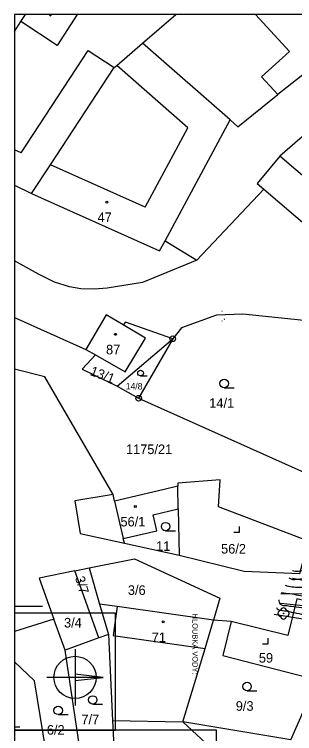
# Model space of a CAD drawing. Extents: x -564091 to -563943, y -1163604 to -1163394.
# Drawn here: x -564091.1 to -564041.3, y -1163521.5 to -1163393.9 of the extents above; entities that cross this region are included whole.
import ezdxf

# ---------------------------------------------------------------- set-up
doc = ezdxf.new("R2010")
doc.units = 0
for name, color, linetype in [('_rám PRU1 a PRI1', 7, 'Continuous'), ('Hranice parcel', 7, 'Continuous'), ('Parcelní čísla', 7, 'Continuous'), ('Vnitřní kresba', 7, 'Continuous'), ('Vrstva 14', 7, 'Continuous'), ('Vrstva 22', 7, 'Continuous'), ('Vrstva 24', 7, 'Continuous'), ('Vrstva 26', 7, 'Continuous'), ('Značky bodu BP', 7, 'Continuous'), ('Značky budov', 7, 'Continuous'), ('Značky kultur', 7, 'Continuous')]:
    doc.layers.add(name, color=color, linetype=linetype)

msp = doc.modelspace()

# ---------------------------------------------------------------- linework, layer by layer
for p, q in [((-564054.1945627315, -1163446.636668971), (-564054.2954721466, -1163446.641197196)), ((-564054.1918225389, -1163448.3497116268), (-564054.2927319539, -1163448.3542398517)), ((-564053.7909211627, -1163448.0049589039), (-564053.8918305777, -1163448.0094871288))]:
    msp.add_line(p, q)
at = {"layer": '_rám PRU1 a PRI1'}
for p, q in [((-564091.1178187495, -1163393.9081689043), (-564091.1178187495, -1163603.908169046)), ((-563942.617818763, -1163393.9081689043), (-564091.1178187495, -1163393.9081689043)), ((-564091.1178187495, -1163498.9081689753), (-564086.1178187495, -1163498.9081689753)), ((-564073.1724956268, -1163500.11602324), (-564091.1178187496, -1163500.1077130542)), ((-564091.1178187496, -1163500.1077130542), (-564091.1178187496, -1163520.8811005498)), ((-564073.1724956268, -1163520.8811005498), (-564073.1724956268, -1163500.11602324)), ((-564080.3449498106, -1163506.5280350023), (-564080.3449498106, -1163516.5280350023)), ((-564075.3449498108, -1163511.5280350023), (-564080.3449498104, -1163510.9530350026)), ((-564075.3449498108, -1163511.5280350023), (-564085.3449498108, -1163511.5280350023)), ((-564055.2271725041, -1163520.8811005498), (-564091.1178187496, -1163520.8811005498)), ((-564091.1178187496, -1163520.8811005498), (-564091.1178187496, -1163603.908169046)), ((-564091.1178187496, -1163520.8811005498), (-564073.1724956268, -1163520.8811005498)), ((-564055.2271725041, -1163603.908169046), (-564055.2271725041, -1163520.8811005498))]:
    msp.add_line(p, q, dxfattribs=at)
msp.add_lwpolyline([(-564075.3449498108, -1163511.5280350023), (-564080.3449498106, -1163511.5280350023), (-564080.3449498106, -1163512.1030350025)], close=True, dxfattribs=at)
msp.add_circle((-564080.3449498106, -1163511.5280350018), 3.750000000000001, dxfattribs=at)
at = {"layer": 'Hranice parcel'}
for p, q in [((-564091.1178187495, -1163424.1901119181), (-564088.0600000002, -1163425.6700000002)), ((-564058.7000000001, -1163437.5200000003), (-564046.8300000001, -1163424.9100000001)), ((-564046.8300000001, -1163424.9100000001), (-564025.3400000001, -1163443.25)), ((-564064.31, -1163434.0900000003), (-564058.7000000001, -1163437.5200000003)), ((-564058.7000000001, -1163437.5200000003), (-564068.36, -1163441.46)), ((-564074.8, -1163447.22), (-564078.4, -1163453.3300000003)), ((-564071.8, -1163448.98), (-564074.8, -1163447.22)), ((-564067.8200000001, -1163451.3300000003), (-564071.8, -1163448.98)), ((-564071.4200000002, -1163457.34), (-564067.8200000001, -1163451.3300000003)), ((-564072.88, -1163459.86), (-564063.0000000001, -1163451.45)), ((-564063.0000000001, -1163451.45), (-564069.05, -1163462)), ((-564078.4, -1163453.3300000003), (-564076.72, -1163454.3200000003)), ((-564076.72, -1163454.3200000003), (-564071.4200000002, -1163457.34)), ((-564072.88, -1163459.86), (-564069.05, -1163462)), ((-564069.05, -1163462), (-564039.04, -1163475.4300000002)), ((-564062.0000000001, -1163481.6300000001), (-564062.0700000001, -1163477.6300000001)), ((-564062.0000000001, -1163481.6300000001), (-564061.85, -1163489.8700000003)), ((-564071.5700000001, -1163487.74), (-564061.85, -1163489.8700000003)), ((-564080.36, -1163492.6300000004), (-564077.8600000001, -1163492.12)), ((-564077.8600000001, -1163492.12), (-564075.98, -1163498.54)), ((-564076.1, -1163504.52), (-564080.36, -1163492.6300000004)), ((-564075.98, -1163498.54), (-564074.41, -1163503.9000000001)), ((-564084.1, -1163501.1700000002), (-564091.1178187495, -1163503.3904184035)), ((-564082.12, -1163506.7), (-564084.1, -1163501.1700000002)), ((-564052.5900000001, -1163501.62), (-564055.7800000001, -1163501.3900000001)), ((-564076.1, -1163504.52), (-564082.12, -1163506.7)), ((-564074.41, -1163503.9000000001), (-564076.1, -1163504.52)), ((-564074.41, -1163503.9000000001), (-564073.7100000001, -1163519.1600000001)), ((-564078.72, -1163529.1500000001), (-564082.12, -1163506.7)), ((-564042.03, -1163522.61), (-564037.3400000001, -1163511.95)), ((-564073.7100000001, -1163519.1600000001), (-564061.18, -1163519.3900000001)), ((-564042.03, -1163522.61), (-564061.18, -1163519.3900000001))]:
    msp.add_line(p, q, dxfattribs=at)
for points in [[(-564091.1178187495, -1163396.9348794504), (-564089.99, -1163395.2), (-564089.1477261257, -1163393.9081689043)], [(-564088.0600000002, -1163425.6700000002), (-564084.72, -1163420.59), (-564073.39, -1163403.36), (-564072.9400000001, -1163402.97), (-564068.35, -1163399.01), (-564062.4303181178, -1163393.9081689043)], [(-564044.3500000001, -1163408.1300000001), (-564047.22, -1163404.99), (-564042.28, -1163400.47), (-564048.2735600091, -1163393.9081689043)], [(-564016.0603817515, -1163393.9081689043), (-564018.3400000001, -1163396.8800000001), (-564043.9700000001, -1163419.09), (-564048.02, -1163423.8900000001), (-564046.8300000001, -1163424.9100000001)], [(-564023.206475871, -1163393.9081689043), (-564033.27, -1163399.45), (-564044.3500000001, -1163408.1300000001)], [(-564064.31, -1163434.0900000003), (-564052.8, -1163412.6400000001), (-564051.4500000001, -1163413.83), (-564044.3500000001, -1163408.1300000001)], [(-564088.0600000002, -1163425.6700000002), (-564065.3300000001, -1163435.84), (-564064.31, -1163434.0900000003)], [(-564068.36, -1163441.46), (-564074.6300000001, -1163442.46), (-564076.93, -1163442.6700000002), (-564079.29, -1163442.57), (-564081.35, -1163442.23), (-564084.01, -1163441.4000000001), (-564086.8400000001, -1163439.97), (-564091.1178187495, -1163437.610531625)], [(-564030.62, -1163449.1700000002), (-564050.55, -1163447.07), (-564055.2000000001, -1163447.28), (-564061.43, -1163449.5000000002), (-564063.0000000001, -1163451.45)], [(-564091.1178187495, -1163447.6580384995), (-564078.4, -1163453.3300000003)], [(-564063.0000000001, -1163451.45), (-564071.36, -1163448.5), (-564071.8, -1163448.98)], [(-564076.72, -1163454.3200000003), (-564079.0700000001, -1163456.87), (-564072.88, -1163459.86)], [(-564073.5900000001, -1163479.1), (-564085.6900000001, -1163458.23), (-564091.1178187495, -1163456.8425682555)], [(-564038.9, -1163487.37), (-564054.87, -1163481.26), (-564054.55, -1163476.46), (-564062.0800000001, -1163477.1), (-564062.0700000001, -1163477.6300000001)], [(-564062.0700000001, -1163477.6300000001), (-564064.51, -1163478.1700000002), (-564073.3200000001, -1163480.27), (-564073.5900000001, -1163479.1)], [(-564073.5900000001, -1163479.1), (-564080.4, -1163480.2), (-564079.43, -1163486.0000000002), (-564071.5700000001, -1163487.74)], [(-564071.5700000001, -1163487.74), (-564071.77, -1163486.8900000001), (-564065.8300000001, -1163485.5), (-564066.49, -1163482.6800000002), (-564062.0000000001, -1163481.6300000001)], [(-564061.85, -1163489.8700000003), (-564050.3300000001, -1163492.71), (-564040.4, -1163493.1), (-564038.9, -1163487.37)], [(-564077.8600000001, -1163492.12), (-564069.8100000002, -1163490.48), (-564054.63, -1163497.4700000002), (-564055.7800000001, -1163501.3900000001)], [(-564080.36, -1163492.6300000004), (-564086.6900000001, -1163493.9200000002), (-564084.1, -1163501.1700000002)], [(-564055.7800000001, -1163501.3900000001), (-564072.88, -1163498.98), (-564075.98, -1163498.54)], [(-564034.5200000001, -1163499.22), (-564040.98, -1163497.58), (-564042.5800000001, -1163504.09), (-564052.5900000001, -1163501.62)], [(-564061.18, -1163519.3900000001), (-564057.24, -1163506.3800000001), (-564055.7800000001, -1163501.3900000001)], [(-564052.5900000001, -1163501.62), (-564054.0700000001, -1163507.6400000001), (-564037.3400000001, -1163511.95)], [(-564084.4600000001, -1163530.9400000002), (-564087.5700000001, -1163512.11), (-564091.1178187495, -1163508.7789923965)], [(-564073.7100000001, -1163519.1600000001), (-564073.26, -1163527.4200000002), (-564078.72, -1163529.1500000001)], [(-564052.86, -1163559.2), (-564050.52, -1163529.28), (-564061.18, -1163519.3900000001)]]:
    msp.add_lwpolyline(points, dxfattribs=at)
at = {"layer": 'Vnitřní kresba'}
for p, q in [((-564079.966598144, -1163393.9081689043), (-564083.53, -1163399.4000000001)), ((-564083.53, -1163399.4000000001), (-564089.99, -1163395.2)), ((-564052.8, -1163412.6400000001), (-564068.35, -1163399.01)), ((-564089.92, -1163418.49), (-564077.99, -1163400.34)), ((-564077.99, -1163400.34), (-564073.39, -1163403.36)), ((-564060.3400000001, -1163414.0100000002), (-564072.9400000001, -1163402.97)), ((-564067.91, -1163428.11), (-564060.3400000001, -1163414.0100000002)), ((-564089.92, -1163418.49), (-564091.1178187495, -1163417.9102433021)), ((-564025.9000000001, -1163434.5100000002), (-564043.9700000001, -1163419.09)), ((-564067.91, -1163428.11), (-564084.72, -1163420.59)), ((-564073.3200000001, -1163480.27), (-564071.77, -1163486.8900000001)), ((-564072.88, -1163498.98), (-564073.5800000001, -1163504.0800000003)), ((-564073.5800000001, -1163504.0800000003), (-564057.24, -1163506.3800000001))]:
    msp.add_line(p, q, dxfattribs=at)
at = {"layer": 'Vrstva 14'}
for points in [[(-564039.28, -1163487.75), (-564036.8400000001, -1163489.4200000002), (-564038.8, -1163494.54), (-564041.7500000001, -1163494)], [(-564043.78, -1163496.6800000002), (-564039.11, -1163496.6500000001), (-564033.65, -1163495.1), (-564026.22, -1163496.05), (-564024.87, -1163494.3900000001), (-564018.75, -1163494.79), (-564015.5, -1163495.09), (-564011.97, -1163494.31)], [(-564043.87, -1163498.35), (-564039.27, -1163498.85), (-564035.16, -1163499.22), (-564031.7200000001, -1163499.8800000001), (-564029.5900000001, -1163502.8600000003)], [(-564044.99, -1163500.33), (-564033.7200000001, -1163502.1600000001), (-564029.5900000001, -1163502.8600000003), (-564026.18, -1163503.55), (-564027.15, -1163505), (-564030.15, -1163509.57), (-564034.03, -1163515.1500000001), (-564041.7400000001, -1163526.9000000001)]]:
    msp.add_lwpolyline(points, dxfattribs=at)
at = {"layer": 'Vrstva 22'}
msp.add_circle((-564043.31, -1163500.1800000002), 0.05, dxfattribs=at)
for centre, start, end in [((-564043.81, -1163500.1800000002), 90, 270), ((-564043.31, -1163499.6800000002), 0, 180), ((-564042.81, -1163500.1800000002), 270, 89.99999999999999), ((-564043.31, -1163500.6800000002), 180, 0)]:
    msp.add_arc(centre, 0.5000000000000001, start, end, dxfattribs=at)
at = {"layer": 'Vrstva 24'}
for points in [[(-564041.72, -1163492.59), (-564041.2324006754, -1163492.6902851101), (-564040.2442296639, -1163492.5954321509), (-564037.9335213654, -1163492.2765456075), (-564035.2812670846, -1163491.8801688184), (-564033.90521669, -1163491.6549202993), (-564033.758353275, -1163491.6427784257), (-564032.6964996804, -1163491.6793649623), (-564031.719695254, -1163491.6486639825), (-564030.3311891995, -1163491.539192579), (-564028.2728326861, -1163491.2886770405), (-564027.7383065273, -1163491.1901806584), (-564025.74, -1163490.9200000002)], [(-564043.01, -1163495.1600000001), (-564042.7035521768, -1163495.2588767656), (-564040.2491042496, -1163495.5065809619), (-564038.9332366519, -1163495.4468688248), (-564035.5647167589, -1163494.8917977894), (-564033.8408276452, -1163494.6229308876), (-564033.3537459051, -1163494.5703051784), (-564033.1471364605, -1163494.5604693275), (-564027.1638547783, -1163493.8608311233), (-564025.6244990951, -1163493.5482974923), (-564022.0841546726, -1163493.0890306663), (-564020.7770882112, -1163493.0390634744), (-564020.3447589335, -1163492.9752743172), (-564019.2047595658, -1163492.8313547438), (-564014.6979277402, -1163492.660362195), (-564013.1556355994, -1163492.6561344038), (-564012.2308436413, -1163492.6145163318), (-564007.8600000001, -1163491.79)], [(-564044.14, -1163497.77), (-564043.9458102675, -1163498.4840217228), (-564043.7872880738, -1163498.6202907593), (-564042.8764787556, -1163498.7711677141), (-564041.9651982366, -1163498.9038277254), (-564040.1390941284, -1163499.1361126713), (-564038.4597870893, -1163499.3332080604), (-564036.7908988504, -1163499.3811019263), (-564035.9548747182, -1163499.345412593), (-564035.2869542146, -1163499.3067557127)]]:
    msp.add_spline(points, degree=3, dxfattribs=at)
at = {"layer": 'Vrstva 26'}
for points in [[(-564042.3700000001, -1163493.8700000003), (-564041.8339702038, -1163494.1108572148), (-564041.5981714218, -1163494.1524036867), (-564041.0666092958, -1163494.125095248), (-564038.5321072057, -1163493.8401984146), (-564034.433403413, -1163493.2183632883), (-564034.3090436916, -1163493.1939145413), (-564034.1949362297, -1163493.1933293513), (-564032.5345471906, -1163493.105598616), (-564031.7419114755, -1163493.052780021), (-564027.7191473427, -1163492.572890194), (-564026.6669285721, -1163492.385386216), (-564022.75, -1163491.86)], [(-564043.66, -1163496.45), (-564043.6157657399, -1163496.4631784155), (-564042.1824033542, -1163496.6697370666), (-564039.1481388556, -1163497.1744092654), (-564038.2736075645, -1163497.1941844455), (-564037.268923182, -1163497.097417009), (-564036.2661365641, -1163496.955123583), (-564035.262299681, -1163496.8211313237), (-564034.2544645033, -1163496.749267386), (-564034.2452516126, -1163496.7490500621)], [(-564044.5800000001, -1163499.1), (-564044.4381619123, -1163499.354429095), (-564043.4689350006, -1163499.6606231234), (-564042.3386667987, -1163499.8602294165), (-564040.5565955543, -1163500.2129695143), (-564038.777798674, -1163500.5823265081), (-564035.4614926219, -1163501.229193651)]]:
    msp.add_spline(points, degree=3, dxfattribs=at)
at = {"layer": 'Značky bodu BP'}
for centre, radius in [((-564063.0000000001, -1163451.4498797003), 0.5000013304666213), ((-564063.0000000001, -1163451.4498797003), 0.03030008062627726), ((-564069.05, -1163461.9998797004), 0.5000013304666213), ((-564069.05, -1163461.9998797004), 0.03030008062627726)]:
    msp.add_circle(centre, radius, dxfattribs=at)
at = {"layer": 'Značky budov'}
msp.add_line((-564084.5773142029, -1163393.9081689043), (-564084.8762857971, -1163393.9081689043), dxfattribs=at)
for centre in [(-564074.6768, -1163427.199157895), (-564073.1668, -1163450.6691578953), (-564069.6368, -1163481.199157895), (-564064.6968, -1163501.6691578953)]:
    msp.add_circle(centre, 0.17500000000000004, dxfattribs=at)
msp.add_arc((-564084.7268000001, -1163393.9991578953), 0.17500000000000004, 148.67196830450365, 31.328031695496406, dxfattribs=at)
at = {"layer": 'Značky kultur'}
for p, q in [((-564068.7150000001, -1163458.04), (-564067.5430000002, -1163458.04)), ((-564053.853, -1163460.1500000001), (-564052.1030000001, -1163460.1500000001)), ((-564064.263, -1163485.53), (-564062.513, -1163485.53)), ((-564052.1410000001, -1163485.78), (-564051.14, -1163485.78)), ((-564051.14, -1163485.78), (-564051.14, -1163484.78)), ((-564046.05, -1163505.57), (-564046.05, -1163504.57)), ((-564047.051, -1163505.57), (-564046.05, -1163505.57)), ((-564049.7930000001, -1163513.9000000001), (-564048.0430000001, -1163513.9000000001)), ((-564077.203, -1163516.28), (-564075.453, -1163516.28)), ((-564083.343, -1163518.1400000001), (-564081.5930000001, -1163518.1400000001)), ((-564091.1178187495, -1163520.3100000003), (-564090.123, -1163520.3100000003))]:
    msp.add_line(p, q, dxfattribs=at)
for centre, radius in [((-564068.7152142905, -1163457.5373745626), 0.5024994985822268), ((-564053.85285715, -1163459.39981278), 0.7499992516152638), ((-564064.26285715, -1163484.77981278), 0.7499992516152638), ((-564049.79285715, -1163513.14981278), 0.7499992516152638), ((-564077.20285715, -1163515.52981278), 0.7499992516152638), ((-564083.34285715, -1163517.38981278), 0.7499992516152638)]:
    msp.add_circle(centre, radius, dxfattribs=at)

# ---------------------------------------------------------------- texts
at = {"layer": '_rám PRU1 a PRI1'}
msp.add_text('HLOUBKA VODY:', height=0.9559649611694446, rotation=270, dxfattribs=at).set_placement((-564059.4971589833, -1163500.2217355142))
at = {"layer": 'Parcelní čísla'}
for s, height, p in [('47', 1.6999980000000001, (-564076.346, -1163430.75)), ('87', 1.6999980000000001, (-564074.836, -1163454.22)), ('14/8', 1.1400000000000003, (-564071.336, -1163460.45)), ('14/1', 1.6999980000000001, (-564056.5090000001, -1163463.7)), ('1175/21', 1.6999980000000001, (-564071.3, -1163471.9100000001)), ('56/1', 1.6999980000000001, (-564072.279, -1163484.75)), ('11', 1.6999980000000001, (-564065.946, -1163489.08)), ('56/2', 1.6999980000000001, (-564054.4090000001, -1163489.56)), ('3/6', 1.6999980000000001, (-564070.9600000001, -1163496.8900000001)), ('3/4', 1.6999980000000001, (-564082.3, -1163502.6800000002)), ('71', 1.6999980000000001, (-564066.726, -1163505.2800000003)), ('59', 1.6999980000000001, (-564047.696, -1163508.9100000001)), ('9/3', 1.6999980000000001, (-564051.8, -1163517.45)), ('7/7', 1.6999980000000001, (-564079.2100000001, -1163519.83)), ('6/2', 1.6999980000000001, (-564085.35, -1163521.69))]:
    msp.add_text(s, height=height, dxfattribs=at).set_placement(p)
for s, height, rotation, p in [('13/1', 1.6999979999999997, 339, (-564077.818, -1163457.8440000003)), ('3/7', 1.6999980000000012, 286, (-564080.358, -1163493.8310000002))]:
    msp.add_text(s, height=height, rotation=rotation, dxfattribs=at).set_placement(p)

doc.saveas('drawing.dxf')
